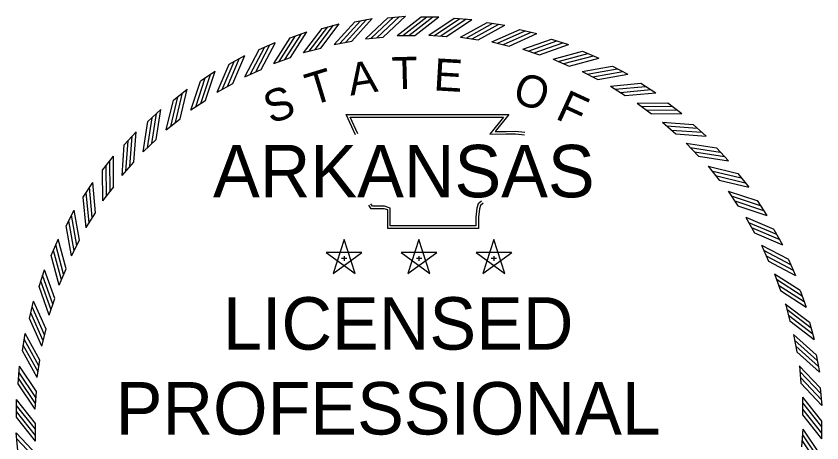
# Model space of a CAD drawing. Extents: x 16 to 1228740, y 11 to 152440.
# Drawn here: x 18.963 to 19.1351, y 11.081 to 11.1721 of the extents above; entities that cross this region are included whole.
import ezdxf

# ---------------------------------------------------------------- set-up
doc = ezdxf.new("R2010")
doc.units = 0
doc.layers.add('STAMP_JUSTIN', color=7, linetype='Continuous')

msp = doc.modelspace()

# ---------------------------------------------------------------- linework, layer by layer
at = {"layer": 'STAMP_JUSTIN'}
for p, q in [((19.04238, 11.17178), (19.04613, 11.17213)), ((19.02836, 11.16952), (19.03201, 11.17047)), ((19.03532, 11.17094), (19.03903, 11.17159)), ((19.04952, 11.17199), (19.05329, 11.17199)), ((19.05658, 11.17171), (19.06034, 11.17143)), ((19.06363, 11.17079), (19.06735, 11.17021)), ((19.02154, 11.16752), (19.02509, 11.16878)), ((19.07057, 11.1693), (19.07424, 11.16841)), ((19.03762, 11.16731), (19.04139, 11.16766)), ((19.04437, 11.16798), (19.04815, 11.16798)), ((19.05115, 11.16809), (19.05492, 11.16781)), ((19.05792, 11.16763), (19.06165, 11.16704)), ((19.07737, 11.16724), (19.08095, 11.16605)), ((19.0149, 11.16497), (19.01834, 11.16652)), ((19.0244, 11.16433), (19.02806, 11.16529)), ((19.03095, 11.16609), (19.03467, 11.16675)), ((19.06463, 11.16662), (19.0683, 11.16573)), ((19.0085, 11.16188), (19.0118, 11.16371)), ((19.07122, 11.16506), (19.07481, 11.16386)), ((19.08398, 11.16462), (19.08745, 11.16314)), ((19.01803, 11.16203), (19.02159, 11.16328)), ((19.07767, 11.16296), (19.08115, 11.16147)), ((19.00238, 11.15828), (19.00552, 11.16037)), ((19.01186, 11.1592), (19.0153, 11.16075)), ((19.08393, 11.16033), (19.08726, 11.15856)), ((19.09035, 11.16147), (19.09368, 11.1597)), ((19.00594, 11.15588), (19.00925, 11.15771)), ((19.08994, 11.15719), (19.09312, 11.15516)), ((19.09643, 11.1578), (19.09961, 11.15577)), ((18.99658, 11.15418), (18.99953, 11.15652)), ((19.00033, 11.15209), (19.00347, 11.15418)), ((19.09567, 11.15357), (19.09868, 11.15128)), ((19.1022, 11.15364), (19.10519, 11.15135)), ((18.99113, 11.14961), (18.99388, 11.15219)), ((18.99504, 11.14784), (18.998, 11.15019)), ((19.10109, 11.14949), (19.10389, 11.14696)), ((19.1076, 11.14902), (19.11039, 11.14649)), ((18.98608, 11.14461), (18.98861, 11.14741)), ((18.99012, 11.14317), (18.99288, 11.14575)), ((19.10615, 11.14498), (19.10873, 11.14222)), ((19.1126, 11.14397), (19.11517, 11.14122)), ((18.98146, 11.13921), (18.98375, 11.14221)), ((18.98561, 11.13811), (18.98814, 11.14091)), ((19.11082, 11.14006), (19.11317, 11.1371)), ((19.11716, 11.13852), (19.1195, 11.13557)), ((18.9773, 11.13345), (18.97933, 11.13663)), ((18.98153, 11.13269), (18.98382, 11.13569)), ((19.11507, 11.13477), (19.11716, 11.13163)), ((19.12126, 11.13272), (19.12335, 11.12958)), ((18.97363, 11.12737), (18.9754, 11.1307)), ((18.97791, 11.12696), (18.97994, 11.13014)), ((19.11887, 11.12915), (19.1207, 11.12585)), ((19.12487, 11.12659), (19.12669, 11.1233)), ((18.97048, 11.121), (18.97196, 11.12446)), ((18.97477, 11.12094), (18.97654, 11.12428)), ((19.03304, 11.12443), (19.03068, 11.11719)), ((19.03539, 11.11719), (19.03305, 11.12443)), ((19.04903, 11.12443), (19.04668, 11.11719)), ((19.05138, 11.11719), (19.04904, 11.12443)), ((19.06502, 11.12443), (19.06267, 11.11719)), ((19.06737, 11.11719), (19.06503, 11.12443)), ((19.12219, 11.12324), (19.12374, 11.1198)), ((19.03684, 11.12166), (19.02923, 11.12167)), ((19.02924, 11.12166), (19.03539, 11.11718)), ((19.03069, 11.11719), (19.03685, 11.12166)), ((19.0325, 11.12045), (19.03363, 11.12045)), ((19.03305, 11.12085), (19.03305, 11.1199)), ((19.05284, 11.12166), (19.04523, 11.12167)), ((19.04523, 11.12166), (19.05138, 11.11718)), ((19.04668, 11.11719), (19.05285, 11.12166)), ((19.04849, 11.12045), (19.04962, 11.12045)), ((19.04904, 11.12085), (19.04904, 11.1199)), ((19.06883, 11.12166), (19.06122, 11.12167)), ((19.06122, 11.12166), (19.06738, 11.11718)), ((19.06267, 11.11719), (19.06884, 11.12166)), ((19.06448, 11.12045), (19.06561, 11.12045)), ((19.06503, 11.12085), (19.06503, 11.1199)), ((19.12796, 11.12019), (19.1295, 11.11676)), ((18.96786, 11.11439), (18.96905, 11.11797)), ((18.97214, 11.11469), (18.97363, 11.11816)), ((19.12501, 11.11707), (19.12627, 11.11351)), ((19.1305, 11.11356), (19.13176, 11.11001)), ((18.97004, 11.10824), (18.97124, 11.11183)), ((18.9658, 11.10759), (18.96669, 11.11125)), ((19.12731, 11.11069), (19.12827, 11.10704)), ((19.1325, 11.10674), (19.13346, 11.10309)), ((18.96848, 11.10164), (18.96937, 11.10531)), ((18.96431, 11.10064), (18.96489, 11.10437)), ((19.12908, 11.10415), (19.12973, 11.10043)), ((19.13392, 11.09978), (19.13458, 11.09607)), ((18.96747, 11.09494), (18.96806, 11.09867)), ((18.96339, 11.0936), (18.96367, 11.09736)), ((19.1303, 11.09748), (19.13064, 11.09371)), ((18.96701, 11.08817), (18.96729, 11.09194)), ((19.13476, 11.09272), (19.13511, 11.08897)), ((18.96306, 11.0865), (18.96303, 11.09027)), ((19.13096, 11.09073), (19.131, 11.08695)), ((18.96712, 11.08139), (18.96708, 11.08517)), ((19.13502, 11.08562), (19.13506, 11.08185)), ((18.96332, 11.0794), (18.96297, 11.08315)), ((19.13107, 11.08395), (19.13079, 11.08018))]:
    msp.add_line(p, q, dxfattribs=at)
for points in [[(19.04138, 11.16766), (19.04614, 11.17213)], [(19.02805, 11.16529), (19.03201, 11.17048)], [(19.03095, 11.16609), (19.03532, 11.17093)], [(19.03215, 11.16629), (19.03651, 11.17113)], [(19.03343, 11.16655), (19.0378, 11.17139)], [(19.03467, 11.16675), (19.03904, 11.1716)], [(19.03762, 11.16731), (19.04237, 11.17178)], [(19.03883, 11.16741), (19.04358, 11.17188)], [(19.04013, 11.16756), (19.04488, 11.17203)], [(19.04437, 11.16798), (19.04951, 11.17199)], [(19.04558, 11.16797), (19.05072, 11.17198)], [(19.04689, 11.16799), (19.05203, 11.17201)], [(19.04815, 11.16798), (19.05329, 11.17199)], [(19.05115, 11.16808), (19.05657, 11.17171)], [(19.05236, 11.16798), (19.05778, 11.17161)], [(19.05367, 11.16791), (19.05909, 11.17154)], [(19.05492, 11.16781), (19.06034, 11.17143)], [(19.05791, 11.16763), (19.06362, 11.17079)], [(19.05911, 11.16743), (19.06482, 11.17059)], [(19.06041, 11.16725), (19.06611, 11.17042)], [(19.02158, 11.16329), (19.02509, 11.16878)], [(19.0244, 11.16432), (19.02835, 11.16951)], [(19.02558, 11.16462), (19.02953, 11.16981)], [(19.02684, 11.16498), (19.03079, 11.17017)], [(19.06165, 11.16705), (19.06735, 11.17021)], [(19.06462, 11.16662), (19.07057, 11.1693)], [(19.0658, 11.16632), (19.07174, 11.169)], [(19.06708, 11.16604), (19.07302, 11.16872)], [(19.01802, 11.16202), (19.02153, 11.16752)], [(19.01917, 11.16241), (19.02268, 11.16791)], [(19.02039, 11.16288), (19.02391, 11.16838)], [(19.06829, 11.16573), (19.07424, 11.16841)], [(19.07122, 11.16506), (19.07737, 11.16724)], [(19.01297, 11.15969), (19.01601, 11.16546)], [(19.01415, 11.16025), (19.0172, 11.16602)], [(19.0153, 11.16075), (19.01835, 11.16652)], [(19.07237, 11.16466), (19.07851, 11.16684)], [(19.07362, 11.16427), (19.07977, 11.16646)], [(19.07481, 11.16387), (19.08095, 11.16605)], [(19.00925, 11.15771), (19.01181, 11.16371)], [(19.01186, 11.1592), (19.0149, 11.16497)], [(19.07767, 11.16295), (19.08397, 11.16462)], [(19.07878, 11.16247), (19.08509, 11.16413)], [(19.07999, 11.16198), (19.0863, 11.16364)], [(19.00594, 11.15588), (19.0085, 11.16188)], [(19.00701, 11.15646), (19.00957, 11.16246)], [(19.00814, 11.15712), (19.0107, 11.16312)], [(19.08114, 11.16147), (19.08745, 11.16314)], [(19.00346, 11.15418), (19.00552, 11.16037)], [(19.08392, 11.16033), (19.09034, 11.16147)], [(19.08499, 11.15975), (19.09141, 11.16089)], [(19.08616, 11.15916), (19.09258, 11.1603)], [(19.00134, 11.15275), (19.00339, 11.15894)], [(19.00241, 11.1535), (19.00447, 11.15969)], [(19.08726, 11.15856), (19.09368, 11.1597)], [(19.00032, 11.15208), (19.00238, 11.15827)], [(19.08993, 11.15719), (19.09643, 11.1578)], [(19.09095, 11.15653), (19.09744, 11.15713)], [(18.996, 11.14858), (18.99753, 11.15492)], [(18.997, 11.14941), (18.99854, 11.15575)], [(18.99799, 11.15019), (18.99953, 11.15653)], [(19.09207, 11.15585), (19.09856, 11.15645)], [(19.09312, 11.15516), (19.09961, 11.15577)], [(18.99504, 11.14783), (18.99658, 11.15417)], [(19.09567, 11.15357), (19.10219, 11.15364)], [(18.99287, 11.14575), (18.99388, 11.1522)], [(19.09663, 11.15283), (19.10315, 11.15289)], [(19.09768, 11.15206), (19.10421, 11.15212)], [(18.99101, 11.14398), (18.99202, 11.15043)], [(18.99195, 11.1449), (18.99296, 11.15135)], [(19.03547, 11.14676), (19.03346, 11.15111), (19.06823, 11.15113), (19.06533, 11.14748), (19.06769, 11.14751), (19.06966, 11.14754), (19.07163, 11.14732)], [(19.03597, 11.14699), (19.03432, 11.15056), (19.06709, 11.15058), (19.06417, 11.14692), (19.06769, 11.14696), (19.06963, 11.14699), (19.07157, 11.14678)], [(19.09867, 11.15128), (19.1052, 11.15135)], [(18.99012, 11.14316), (18.99113, 11.14961)], [(19.10108, 11.14949), (19.10759, 11.14902)], [(19.10198, 11.14867), (19.10848, 11.1482)], [(18.98729, 11.13999), (18.98776, 11.14649)], [(18.98814, 11.14091), (18.98861, 11.14742)], [(19.10297, 11.14781), (19.10947, 11.14734)], [(19.10389, 11.14696), (19.1104, 11.14649)], [(18.98561, 11.1381), (18.98608, 11.14461)], [(18.98643, 11.13899), (18.9869, 11.1455)], [(19.10614, 11.14498), (19.11259, 11.14397)], [(19.10697, 11.14409), (19.11341, 11.14308)], [(19.10788, 11.14315), (19.11433, 11.14214)], [(18.98304, 11.1347), (18.98298, 11.14122)], [(18.98381, 11.13569), (18.98375, 11.14222)], [(19.10873, 11.14223), (19.11518, 11.14122)], [(18.98227, 11.13364), (18.9822, 11.14017)], [(19.11082, 11.14006), (19.11715, 11.13852)], [(18.98153, 11.13269), (18.98146, 11.13921)], [(19.11156, 11.1391), (19.1179, 11.13757)], [(19.1124, 11.1381), (19.11874, 11.13656)], [(18.97994, 11.13014), (18.97933, 11.13663)], [(19.11317, 11.1371), (19.11951, 11.13557)], [(18.97857, 11.12797), (18.97796, 11.13446)], [(18.97925, 11.12909), (18.97865, 11.13558)], [(19.11506, 11.13478), (19.12125, 11.13272)], [(18.97791, 11.12695), (18.9773, 11.13345)], [(19.0624, 11.13262), (19.06167, 11.13202), (19.06142, 11.13109), (19.06121, 11.12921), (19.06121, 11.12733), (19.04291, 11.12733), (19.04291, 11.13002), (19.04291, 11.13115), (19.04165, 11.13154), (19.03911, 11.13154), (19.03878, 11.13204)], [(19.11573, 11.13376), (19.12192, 11.1317)], [(19.11648, 11.13269), (19.12267, 11.13063)], [(19.06275, 11.13219), (19.06216, 11.13171), (19.06196, 11.13099), (19.06177, 11.12918), (19.06177, 11.12678), (19.04236, 11.12678), (19.04236, 11.13002), (19.04236, 11.13075), (19.04157, 11.13099), (19.03881, 11.13099), (19.03832, 11.13173)], [(19.11716, 11.13163), (19.12336, 11.12958)], [(18.97594, 11.12318), (18.9748, 11.1296)], [(18.97653, 11.12428), (18.9754, 11.1307)], [(19.11886, 11.12916), (19.12486, 11.1266)], [(18.97477, 11.12094), (18.97363, 11.12736)], [(18.97535, 11.122), (18.97421, 11.12843)], [(19.11944, 11.12809), (19.12544, 11.12553)], [(19.1201, 11.12696), (19.1261, 11.1244)], [(19.1207, 11.12585), (19.1267, 11.12329)], [(18.97363, 11.11816), (18.97196, 11.12447)], [(18.97312, 11.11701), (18.97146, 11.12332)], [(19.12218, 11.12324), (19.12795, 11.1202)], [(18.97215, 11.11468), (18.97048, 11.12099)], [(18.97263, 11.1158), (18.97097, 11.1221)], [(19.12267, 11.12213), (19.12844, 11.11909)], [(19.12323, 11.12095), (19.129, 11.1179)], [(19.12374, 11.1198), (19.12951, 11.11675)], [(18.97123, 11.11182), (18.96905, 11.11797)], [(19.125, 11.11708), (19.1305, 11.11357)], [(18.97044, 11.10938), (18.96826, 11.11553)], [(18.97082, 11.11064), (18.96864, 11.11678)], [(19.1254, 11.11593), (19.13089, 11.11242)], [(18.97004, 11.10824), (18.96786, 11.11438)], [(19.12586, 11.1147), (19.13136, 11.11119)], [(19.12627, 11.11352), (19.13177, 11.11)], [(18.96937, 11.10531), (18.96669, 11.11126)], [(19.1273, 11.1107), (19.13249, 11.10674)], [(18.96878, 11.10281), (18.9661, 11.10876)], [(18.96906, 11.10409), (18.96638, 11.11004)], [(19.1276, 11.10952), (19.13279, 11.10557)], [(18.96848, 11.10164), (18.9658, 11.10758)], [(19.12796, 11.10826), (19.13315, 11.10431)], [(19.12827, 11.10705), (19.13346, 11.10309)], [(18.96805, 11.09867), (18.96489, 11.10437)], [(19.12907, 11.10415), (19.13392, 11.09978)], [(18.96767, 11.09613), (18.96451, 11.10183)], [(18.96785, 11.09743), (18.96468, 11.10313)], [(19.12927, 11.10295), (19.13412, 11.09859)], [(19.12953, 11.10167), (19.13437, 11.0973)], [(18.96747, 11.09493), (18.96431, 11.10064)], [(19.12973, 11.10043), (19.13458, 11.09606)], [(18.96729, 11.09194), (18.96367, 11.09736)], [(19.13029, 11.09748), (19.13476, 11.09273)], [(18.96712, 11.08938), (18.96349, 11.0948)], [(18.96718, 11.09068), (18.96356, 11.09611)], [(19.13039, 11.09627), (19.13486, 11.09152)], [(19.13054, 11.09497), (19.13501, 11.09022)], [(18.96702, 11.08817), (18.96339, 11.09359)], [(19.13065, 11.09372), (19.13511, 11.08896)], [(18.96708, 11.08516), (18.96302, 11.09027)], [(19.13096, 11.09073), (19.13502, 11.08563)], [(19.13096, 11.08952), (19.13502, 11.08441)], [(18.96708, 11.08391), (18.96302, 11.08901)], [(19.131, 11.08821), (19.13506, 11.0831)], [(18.96712, 11.0826), (18.96306, 11.08771)], [(18.96712, 11.08139), (18.96306, 11.08649)], [(19.131, 11.08695), (19.13506, 11.08185)], [(18.96744, 11.0784), (18.96297, 11.08315)], [(19.13096, 11.08274), (19.13459, 11.07732)], [(19.13106, 11.08395), (19.13469, 11.07853)], [(18.96754, 11.07715), (18.96307, 11.0819)], [(19.1309, 11.08143), (19.13452, 11.07601)]]:
    msp.add_lwpolyline(points, dxfattribs=at)

# ---------------------------------------------------------------- texts
for s, rotation, p in [('T', 1.4789, (19.04327, 11.15649)), ('A', 8.6788, (19.03441, 11.15513)), ('E', 356.672, (19.05205, 11.15629)), ('T', 16.9015, (19.02608, 11.15296)), ('O', 341.2218, (19.0687, 11.15393)), ('S', 19.7726, (19.01736, 11.14904)), ('F', 335.3628, (19.07794, 11.15032))]:
    msp.add_text(s, height=0.00686, rotation=rotation, dxfattribs=at).set_placement(p)
for s, height, p in [('ARKANSAS', 0.011194, (19.00504, 11.13344)), ('LICENSED', 0.011194, (19.00717, 11.10091)), ('PROFESSIONAL', 0.0111936, (18.98425, 11.08278))]:
    msp.add_text(s, height=height, dxfattribs=at).set_placement(p)

doc.saveas('drawing.dxf')
